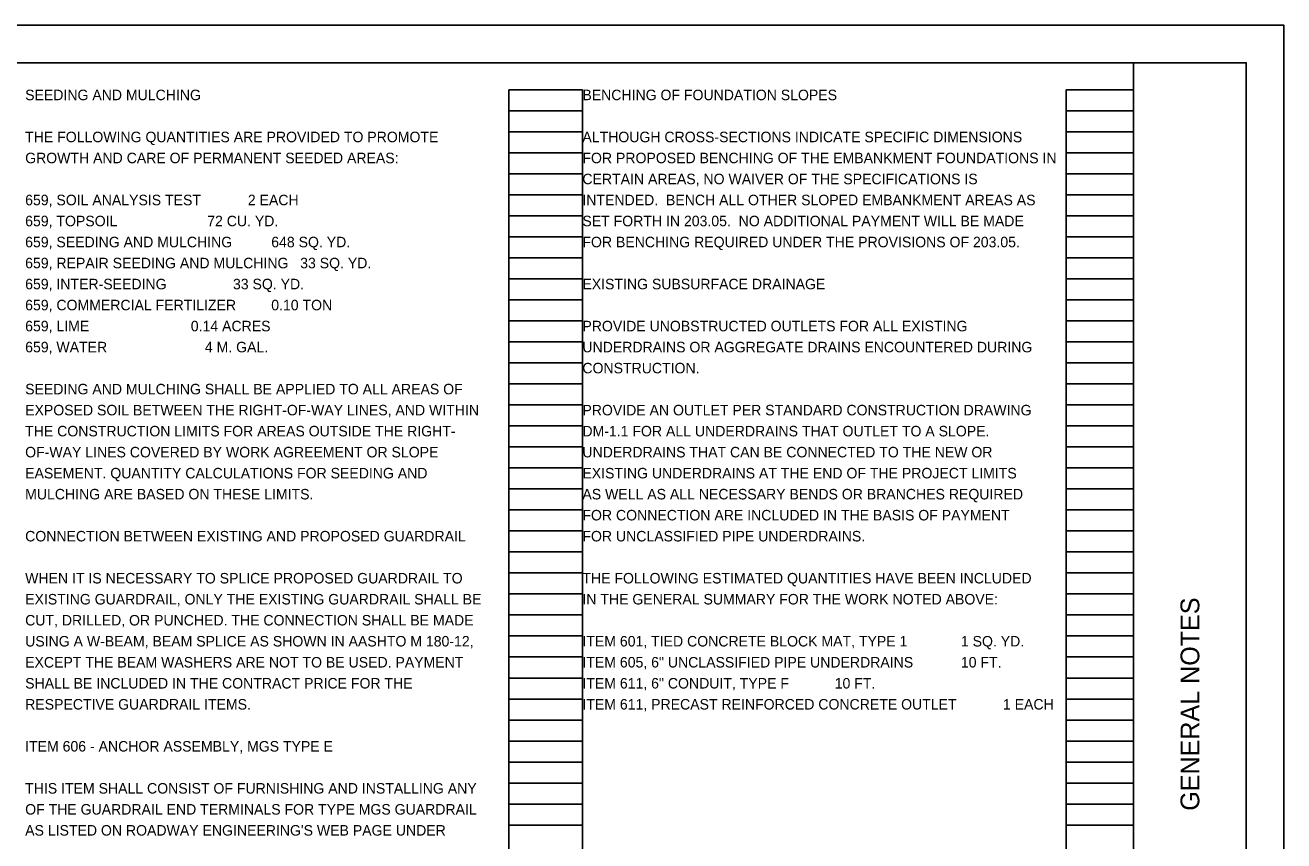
# Model space of a CAD drawing. Extents: x 0 to 34, y 0 to 22.
# Drawn here: x 17.24 to 34, y 11.13 to 22 of the extents above; entities that cross this region are included whole.
import ezdxf

# ---------------------------------------------------------------- set-up
doc = ezdxf.new("R2010")
doc.units = 0
for name, color, linetype in [('SH_Border', 7, 'Continuous'), ('SH_Cut_Line', 7, 'Continuous'), ('SH_Data', 7, 'Continuous'), ('SH_Text', 7, 'Continuous')]:
    doc.layers.add(name, color=color, linetype=linetype)

msp = doc.modelspace()

# ---------------------------------------------------------------- linework, layer by layer
at = {"layer": 'SH_Border'}
msp.add_line((32, 0.5), (32, 21.5), dxfattribs=at)
msp.add_lwpolyline([(1.5, 21.5), (33.5, 21.5), (33.5, 0.5), (1.5, 0.5)], close=True, dxfattribs=at)
at = {"layer": 'SH_Cut_Line'}
msp.add_lwpolyline([(0, 0), (34, 0), (34, 22), (0, 22)], close=True, dxfattribs=at)
at = {"layer": 'SH_Data'}
for p, q in [((23.68, 0.98), (23.68, 21.14)), ((23.68, 21.14), (24.66, 21.14)), ((24.66, 0.98), (24.66, 21.14)), ((31.1, 0.98), (31.1, 21.14)), ((31.1, 21.14), (32, 21.14)), ((32, 0.98), (32, 21.14)), ((23.68, 20.86), (24.66, 20.86)), ((31.1, 20.86), (32, 20.86)), ((23.68, 20.58), (24.66, 20.58)), ((31.1, 20.58), (32, 20.58)), ((23.68, 20.3), (24.66, 20.3)), ((31.1, 20.3), (32, 20.3)), ((23.68, 20.02), (24.66, 20.02)), ((31.1, 20.02), (32, 20.02)), ((23.68, 19.74), (24.66, 19.74)), ((31.1, 19.74), (32, 19.74)), ((23.68, 19.46), (24.66, 19.46)), ((31.1, 19.46), (32, 19.46)), ((23.68, 19.18), (24.66, 19.18)), ((31.1, 19.18), (32, 19.18)), ((23.68, 18.9), (24.66, 18.9)), ((31.1, 18.9), (32, 18.9)), ((23.68, 18.62), (24.66, 18.62)), ((31.1, 18.62), (32, 18.62)), ((23.68, 18.34), (24.66, 18.34)), ((31.1, 18.34), (32, 18.34)), ((23.68, 18.06), (24.66, 18.06)), ((31.1, 18.06), (32, 18.06)), ((23.68, 17.78), (24.66, 17.78)), ((31.1, 17.78), (32, 17.78)), ((23.68, 17.5), (24.66, 17.5)), ((31.1, 17.5), (32, 17.5)), ((23.68, 17.22), (24.66, 17.22)), ((31.1, 17.22), (32, 17.22)), ((23.68, 16.94), (24.66, 16.94)), ((31.1, 16.94), (32, 16.94)), ((23.68, 16.66), (24.66, 16.66)), ((31.1, 16.66), (32, 16.66)), ((23.68, 16.38), (24.66, 16.38)), ((31.1, 16.38), (32, 16.38)), ((23.68, 16.1), (24.66, 16.1)), ((31.1, 16.1), (32, 16.1)), ((23.68, 15.82), (24.66, 15.82)), ((31.1, 15.82), (32, 15.82)), ((23.68, 15.54), (24.66, 15.54)), ((31.1, 15.54), (32, 15.54)), ((23.68, 15.26), (24.66, 15.26)), ((31.1, 15.26), (32, 15.26)), ((23.68, 14.98), (24.66, 14.98)), ((31.1, 14.98), (32, 14.98)), ((23.68, 14.7), (24.66, 14.7)), ((31.1, 14.7), (32, 14.7)), ((23.68, 14.42), (24.66, 14.42)), ((31.1, 14.42), (32, 14.42)), ((23.68, 14.14), (24.66, 14.14)), ((31.1, 14.14), (32, 14.14)), ((23.68, 13.86), (24.66, 13.86)), ((31.1, 13.86), (32, 13.86)), ((23.68, 13.58), (24.66, 13.58)), ((31.1, 13.58), (32, 13.58)), ((23.68, 13.3), (24.66, 13.3)), ((31.1, 13.3), (32, 13.3)), ((23.68, 13.02), (24.66, 13.02)), ((31.1, 13.02), (32, 13.02)), ((23.68, 12.74), (24.66, 12.74)), ((31.1, 12.74), (32, 12.74)), ((23.68, 12.46), (24.66, 12.46)), ((31.1, 12.46), (32, 12.46)), ((23.68, 12.18), (24.66, 12.18)), ((31.1, 12.18), (32, 12.18)), ((23.68, 11.9), (24.66, 11.9)), ((31.1, 11.9), (32, 11.9)), ((23.68, 11.62), (24.66, 11.62)), ((31.1, 11.62), (32, 11.62)), ((23.68, 11.34), (24.66, 11.34)), ((31.1, 11.34), (32, 11.34))]:
    msp.add_line(p, q, dxfattribs=at)

# ---------------------------------------------------------------- texts
msp.add_text('GENERAL NOTES', height=0.25, rotation=90, dxfattribs=at).set_placement((32.875, 11.531))
at = {"layer": 'SH_Text'}
for s, p in [('SEEDING AND MULCHING', (17.24, 21)), ('BENCHING OF FOUNDATION SLOPES', (24.66, 21)), ('THE FOLLOWING QUANTITIES ARE PROVIDED TO PROMOTE', (17.24, 20.44)), ('ALTHOUGH CROSS-SECTIONS INDICATE SPECIFIC DIMENSIONS ', (24.66, 20.44)), ('GROWTH AND CARE OF PERMANENT SEEDED AREAS:', (17.24, 20.16)), ('FOR PROPOSED BENCHING OF THE EMBANKMENT FOUNDATIONS IN ', (24.66, 20.16)), ('CERTAIN AREAS, NO WAIVER OF THE SPECIFICATIONS IS ', (24.66, 19.88)), ('659, SOIL ANALYSIS TEST            2 EACH', (17.24, 19.6)), ('INTENDED.  BENCH ALL OTHER SLOPED EMBANKMENT AREAS AS ', (24.66, 19.6)), ('659, TOPSOIL                       72 CU. YD.', (17.24, 19.32)), ('SET FORTH IN 203.05.  NO ADDITIONAL PAYMENT WILL BE MADE ', (24.66, 19.32)), ('659, SEEDING AND MULCHING          648 SQ. YD.', (17.24, 19.04)), ('FOR BENCHING REQUIRED UNDER THE PROVISIONS OF 203.05.', (24.66, 19.04)), ('659, REPAIR SEEDING AND MULCHING   33 SQ. YD.', (17.24, 18.76)), ('659, INTER-SEEDING                 33 SQ. YD.', (17.24, 18.48)), ('EXISTING SUBSURFACE DRAINAGE', (24.66, 18.48)), ('659, COMMERCIAL FERTILIZER         0.10 TON', (17.24, 18.2)), ('659, LIME                          0.14 ACRES', (17.24, 17.92)), ('PROVIDE UNOBSTRUCTED OUTLETS FOR ALL EXISTING', (24.66, 17.92)), ('659, WATER                         4 M. GAL.', (17.24, 17.64)), ('UNDERDRAINS OR AGGREGATE DRAINS ENCOUNTERED DURING', (24.66, 17.64)), ('CONSTRUCTION.', (24.66, 17.36)), ('SEEDING AND MULCHING SHALL BE APPLIED TO ALL AREAS OF', (17.24, 17.08)), ('EXPOSED SOIL BETWEEN THE RIGHT-OF-WAY LINES, AND WITHIN', (17.24, 16.8)), ('PROVIDE AN OUTLET PER STANDARD CONSTRUCTION DRAWING', (24.66, 16.8)), ('THE CONSTRUCTION LIMITS FOR AREAS OUTSIDE THE RIGHT-', (17.24, 16.52)), ('DM-1.1 FOR ALL UNDERDRAINS THAT OUTLET TO A SLOPE.', (24.66, 16.52)), ('OF-WAY LINES COVERED BY WORK AGREEMENT OR SLOPE', (17.24, 16.24)), ('UNDERDRAINS THAT CAN BE CONNECTED TO THE NEW OR', (24.66, 16.24)), ('EASEMENT. QUANTITY CALCULATIONS FOR SEEDING AND', (17.24, 15.96)), ('EXISTING UNDERDRAINS AT THE END OF THE PROJECT LIMITS', (24.66, 15.96)), ('MULCHING ARE BASED ON THESE LIMITS.', (17.24, 15.68)), ('AS WELL AS ALL NECESSARY BENDS OR BRANCHES REQUIRED', (24.66, 15.68)), ('FOR CONNECTION ARE INCLUDED IN THE BASIS OF PAYMENT', (24.66, 15.4)), ('CONNECTION BETWEEN EXISTING AND PROPOSED GUARDRAIL', (17.24, 15.12)), ('FOR UNCLASSIFIED PIPE UNDERDRAINS.', (24.66, 15.12)), ('WHEN IT IS NECESSARY TO SPLICE PROPOSED GUARDRAIL TO', (17.24, 14.56)), ('THE FOLLOWING ESTIMATED QUANTITIES HAVE BEEN INCLUDED', (24.66, 14.56)), ('EXISTING GUARDRAIL, ONLY THE EXISTING GUARDRAIL SHALL BE', (17.24, 14.28)), ('IN THE GENERAL SUMMARY FOR THE WORK NOTED ABOVE:', (24.66, 14.28)), ('CUT, DRILLED, OR PUNCHED. THE CONNECTION SHALL BE MADE', (17.24, 14)), ('USING A W-BEAM, BEAM SPLICE AS SHOWN IN AASHTO M 180-12,', (17.24, 13.72)), ('ITEM 601, TIED CONCRETE BLOCK MAT, TYPE 1', (24.66, 13.72)), ('1 SQ. YD.', (29.7, 13.72)), ('EXCEPT THE BEAM WASHERS ARE NOT TO BE USED. PAYMENT', (17.24, 13.44)), ('ITEM 605, 6" UNCLASSIFIED PIPE UNDERDRAINS', (24.66, 13.44)), ('10 FT.', (29.7, 13.44)), ('SHALL BE INCLUDED IN THE CONTRACT PRICE FOR THE', (17.24, 13.16)), ('ITEM 611, 6" CONDUIT, TYPE F', (24.66, 13.16)), ('10 FT.', (28.02, 13.16)), ('RESPECTIVE GUARDRAIL ITEMS.', (17.24, 12.88)), ('ITEM 611, PRECAST REINFORCED CONCRETE OUTLET', (24.66, 12.88)), ('1 EACH', (30.26, 12.88)), ('ITEM 606 - ANCHOR ASSEMBLY, MGS TYPE E', (17.24, 12.32)), ('THIS ITEM SHALL CONSIST OF FURNISHING AND INSTALLING ANY', (17.24, 11.76)), ('OF THE GUARDRAIL END TERMINALS FOR TYPE MGS GUARDRAIL', (17.24, 11.48)), ("AS LISTED ON ROADWAY ENGINEERING'S WEB PAGE UNDER", (17.24, 11.2))]:
    msp.add_text(s, height=0.14, dxfattribs=at).set_placement(p)

doc.saveas('drawing.dxf')
